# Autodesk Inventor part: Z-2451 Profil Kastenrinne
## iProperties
Created: 2009-09
Part Number: Z-2451 Profil Kastenrinne
Material: Stahl (hohe Festigk., niedr. Legier.)
Document SubType Name: Sheet Metal
Designer: Strathkötter
Density: 1 g/cm^3
Author: Strathkötter
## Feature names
1. Extrusion2
2. Extrusion3
3. Grobblech1
4. Grobblech3
5. Biegung2
6. Grobblech4
7. Biegung3
8. Grobblech5
9. Biegung4
10. Grobblech6
11. Biegung5
12. Grobblech7
13. Biegung6
14. Grobblech8
15. Biegung7
16. Grobblech9
17. Biegung8
18. Grobblech10
19. Biegung9
20. Grobblech11
21. Biegung10
22. Grobblech12
23. Biegung11
